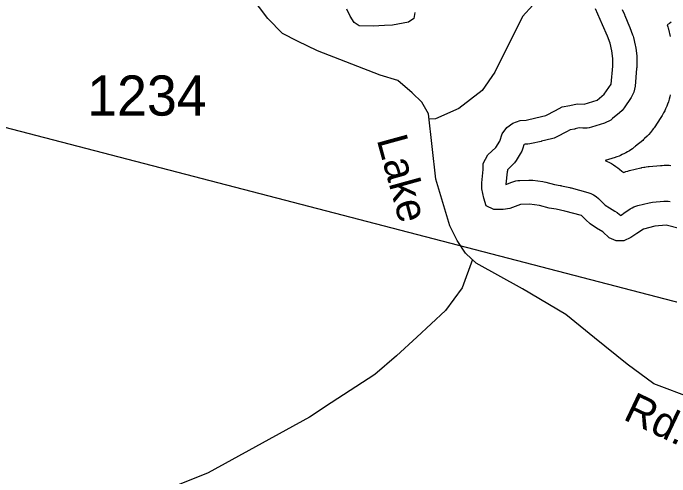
# Model space of a CAD drawing. Extents: x 1113032 to 1302912, y 664689 to 832535.
# Drawn here: x 1149965 to 1152008, y 731794 to 733238 of the extents above; entities that cross this region are included whole.
import ezdxf

# ---------------------------------------------------------------- set-up
doc = ezdxf.new("R2010")
doc.units = 0
for name, color, linetype in [('Exist Hydrographic Buffer Line', 7, 'Continuous'), ('Exist Hydrographic Lake Shore', 7, 'Continuous'), ('Exist Road Non-System Type 51', 7, 'Continuous'), ('Exist Road Secondary Type 51 Attributed', 7, 'Continuous'), ('Exist Road Secondary Type 51 Label', 7, 'Continuous'), ('Exist Road Secondary Type 51 Number Label', 7, 'Continuous'), ('Exist Utilities Electrical Transmission Line', 7, 'Continuous')]:
    doc.layers.add(name, color=color, linetype=linetype)

msp = doc.modelspace()

# ---------------------------------------------------------------- linework, layer by layer
at = {"layer": 'Exist Hydrographic Buffer Line'}
for points in [[(1151859.6, 733249.5), (1151866.9, 733234), (1151867.6, 733232.5), (1151868.3, 733230.9), (1151883, 733195.6), (1151883.6, 733194.3), (1151884.1, 733193), (1151892.5, 733170.5), (1151894, 733166.2), (1151895.2, 733161.9), (1151900.8, 733138.5), (1151901.7, 733134.1), (1151902.4, 733129.6), (1151905.2, 733105.7), (1151905.6, 733100.9), (1151905.7, 733096.1), (1151905.3, 733072.2), (1151905.3, 733069.2), (1151905, 733066.3), (1151899.9, 733010.6), (1151898.5, 733001.4), (1151895.9, 732992.4), (1151892.2, 732983.8), (1151887.5, 732975.7), (1151866.1, 732943.8), (1151859.5, 732935.4), (1151851.9, 732928), (1151830.1, 732909.8), (1151824.2, 732905.4), (1151817.9, 732901.5), (1151811.3, 732898.3), (1151804.5, 732895.8), (1151764.4, 732883.2), (1151757.7, 732881.4), (1151750.9, 732880.3), (1151744.1, 732879.8), (1151737.2, 732879.9), (1151726.2, 732880.6), (1151713.8, 732877.7), (1151712.5, 732877.4), (1151711.2, 732877.1), (1151698, 732874.5), (1151686.4, 732868.7), (1151656.9, 732853.2), (1151648.5, 732849.4), (1151639.8, 732846.7), (1151609.2, 732839.3), (1151608.6, 732839.1), (1151608.1, 732839), (1151577.6, 732832.1), (1151572.1, 732831), (1151566.6, 732830.4), (1151557.9, 732829.8), (1151555.4, 732828.9), (1151554.2, 732828), (1151551.1, 732817.7), (1151547.5, 732808.5), (1151542.7, 732799.7), (1151529.9, 732779.5), (1151524.4, 732771.9), (1151518, 732765.1), (1151502.7, 732750.7), (1151502.6, 732747.3), (1151502.3, 732743.6), (1151498.3, 732705.2), (1151498.3, 732705.1), (1151516.3, 732712.1), (1151522.3, 732714.2), (1151528.5, 732715.8), (1151534.8, 732716.8), (1151541.2, 732717.3), (1151569.2, 732718.3), (1151575.5, 732718.3), (1151581.7, 732717.7), (1151612.8, 732713.5), (1151617.4, 732712.8), (1151621.9, 732711.7), (1151648.8, 732704.7), (1151667.4, 732701.5), (1151669.1, 732701.2), (1151670.7, 732700.9), (1151697.5, 732695.1), (1151699.3, 732694.6), (1151701.2, 732694.2), (1151753.1, 732680.1), (1151762.1, 732677), (1151770.7, 732672.8), (1151778.7, 732667.5), (1151786, 732661.3), (1151798.7, 732648.8), (1151807.5, 732640.6), (1151820.6, 732631.6), (1151837, 732622.1), (1151844.4, 732617.2), (1151851.2, 732611.5), (1151854.8, 732608.1), (1151862.7, 732613.6), (1151863.7, 732614.3), (1151864.7, 732615), (1151885.2, 732628.5), (1151890.8, 732631.9), (1151896.6, 732634.7), (1151902.6, 732637), (1151908.8, 732638.8), (1151944.1, 732647.4), (1151949.4, 732648.5), (1151954.8, 732649.2), (1151989.6, 732652.5), (1151996.1, 732652.8), (1152002.6, 732652.6), (1152009, 732651.8)], [(1152012.1, 733210.2), (1152006.9, 733206.4), (1152000.2, 733201.7), (1152001, 733199.1), (1152002, 733195.8), (1152003.2, 733191.5), (1152003.6, 733189.8), (1152004, 733188.2), (1152009.7, 733164.9)], [(1152009.1, 732984.2), (1152007.9, 732977.3), (1152006.1, 732970.5), (1152003.6, 732961.6), (1152001.4, 732954.9), (1151998.9, 732948.4), (1151995.2, 732939.8), (1151992.3, 732933.5), (1151988.9, 732927.3), (1151984.2, 732919.3), (1151982.4, 732916.3), (1151980.5, 732913.3), (1151959.1, 732881.4), (1151956.8, 732878.1), (1151954.4, 732875), (1151947.9, 732866.6), (1151942.8, 732860.5), (1151937.3, 732854.8), (1151929.6, 732847.4), (1151926.7, 732844.7), (1151923.7, 732842.1), (1151901.9, 732823.8), (1151899.8, 732822.1), (1151897.6, 732820.4), (1151891.7, 732816), (1151887.3, 732812.8), (1151882.7, 732809.8), (1151876.4, 732806), (1151871.7, 732803.3), (1151866.8, 732800.8), (1151860.2, 732797.6), (1151855.2, 732795.3), (1151850.1, 732793.3), (1151843.3, 732790.7), (1151840.7, 732789.8), (1151838.1, 732789), (1151807.5, 732779.4), (1151811.5, 732777.6), (1151820.1, 732773.4), (1151826.4, 732770), (1151832.5, 732766.2), (1151840.5, 732761), (1151846.3, 732756.8), (1151851.9, 732752.3), (1151859.2, 732746.1), (1151861.8, 732743.7), (1151863.6, 732742), (1151866.9, 732743.2), (1151871.5, 732744.6), (1151877.7, 732746.4), (1151880.1, 732747.1), (1151882.4, 732747.7), (1151917.7, 732756.2), (1151919.7, 732756.7), (1151921.6, 732757.1), (1151926.9, 732758.2), (1151930.9, 732758.9), (1151934.9, 732759.5), (1151940.3, 732760.2), (1151942.3, 732760.5), (1151944.3, 732760.7), (1151979.1, 732764), (1151981.5, 732764.2), (1151983.9, 732764.3), (1151990.4, 732764.6), (1151995.2, 732764.8), (1152000.1, 732764.7), (1152006.5, 732764.5), (1152011.4, 732764.2)]]:
    msp.add_lwpolyline(points, dxfattribs=at)
at = {"layer": 'Exist Hydrographic Lake Shore'}
for points in [[(1151214.8, 733240.3), (1151211.7, 733221.8), (1151194.5, 733210.3), (1151144.8, 733201), (1151120, 733199.6), (1151084.8, 733197.5), (1151041.5, 733198.6), (1151026, 733208.7), (1151013.4, 733229.2), (1151003.5, 733251)], [(1151427.8, 732770.2), (1151442.1, 732796.6), (1151466.6, 732819.7), (1151479.4, 732839.9), (1151486.4, 732862.5), (1151500.6, 732881.7), (1151519.9, 732895.9), (1151542.4, 732903.8), (1151561, 732905.2), (1151591.5, 732912.1), (1151622, 732919.6), (1151652.2, 732935.4), (1151673.4, 732946.1), (1151696.7, 732950.7), (1151719.8, 732956.1), (1151741.9, 732954.7), (1151782, 732967.3), (1151803.8, 732985.6), (1151825.2, 733017.5), (1151830.4, 733073.1), (1151830.7, 733097.1), (1151827.9, 733120.9), (1151822.3, 733144.2), (1151813.8, 733166.7), (1151799.1, 733202), (1151791.3, 733218.5), (1151777.1, 733251.1)], [(1151429.4, 732661.6), (1151423.2, 732691.4), (1151423.3, 732709.4), (1151427.7, 732751.4), (1151427.8, 732770.2)], [(1152041.4, 732566.3), (1151996.7, 732577.8), (1151961.8, 732574.5), (1151926.5, 732565.9), (1151906, 732552.4), (1151887.3, 732539.1), (1151865.4, 732529.7), (1151841.5, 732529.4), (1151819.4, 732538.3), (1151799.5, 732557.2), (1151780.4, 732568.2), (1151760.5, 732581.9), (1151747, 732594.4), (1151733.5, 732607.7), (1151681.6, 732621.8), (1151654.8, 732627.6), (1151632.9, 732631.3), (1151602.8, 732639.2), (1151571.8, 732643.4), (1151543.8, 732642.4), (1151510.8, 732629.4), (1151489.9, 732626.4), (1151460.3, 732626.5), (1151436.8, 732637.9), (1151429.4, 732661.6)]]:
    msp.add_lwpolyline(points, dxfattribs=at)
at = {"layer": 'Exist Road Non-System Type 51'}
for points in [[(1151664.2, 733428.6), (1151654.7, 733380.9), (1151581.5, 733262.9), (1151550.2, 733227.7), (1151463.4, 733053.9), (1151423.8, 732996.9), (1151352.1, 732940.9), (1151279.3, 732909.2), (1151259.2, 732908)], [(1151393.7, 732470.6), (1151362.3, 732382.4), (1151309.8, 732312), (1151220.8, 732229.3), (1151157.2, 732170.8), (1151090.5, 732113.5), (1150953.8, 732024.5), (1150887, 731980), (1150572, 731806.7), (1150470.7, 731766.8), (1150266.9, 731623.1), (1150240.5, 731569.5), (1150217.8, 731527.3)]]:
    msp.add_lwpolyline(points, dxfattribs=at)
at = {"layer": 'Exist Road Secondary Type 51 Attributed'}
msp.add_lwpolyline([(1152079.3, 732038.8), (1151958, 732084.1), (1151875.8, 732145.6), (1151773.9, 732227.5), (1151685, 732300.2), (1151549.5, 732380.1), (1151406, 732459.6), (1151390.6, 732473.3), (1151372.6, 732490.4), (1151346.2, 732530.6), (1151323.9, 732575.9), (1151280.4, 732721.7), (1151257.3, 732924.7), (1151236.8, 732960.6), (1151206, 732989.7), (1151161.6, 733028.2), (1151106.6, 733044.9), (1150911.7, 733121), (1150849.4, 733151), (1150802.4, 733174.9), (1150757.1, 733221.1), (1150656.8, 733355)], dxfattribs=at)
at = {"layer": 'Exist Utilities Electrical Transmission Line'}
msp.add_lwpolyline([(1144388.3, 733012.3), (1146921.8, 733668.7), (1152275.9, 732274.5), (1155913.5, 733164.3), (1157133.3, 734480.7), (1157461, 735732.3), (1158252.1, 736454.4), (1158222.6, 737177.7)], dxfattribs=at)

# ---------------------------------------------------------------- texts
at = {"layer": 'Exist Road Secondary Type 51 Label'}
for s, rotation, p in [('Lake', 285.3427, (1151095.6, 732844.7)), ('Rd.', 334.6235, (1151859.6, 731974.6))]:
    msp.add_text(s, height=95, rotation=rotation, dxfattribs=at).set_placement(p)
at = {"layer": 'Exist Road Secondary Type 51 Number Label'}
msp.add_text('1234', height=125, dxfattribs=at).set_placement((1150195.1, 732919.1))

doc.saveas('drawing.dxf')
